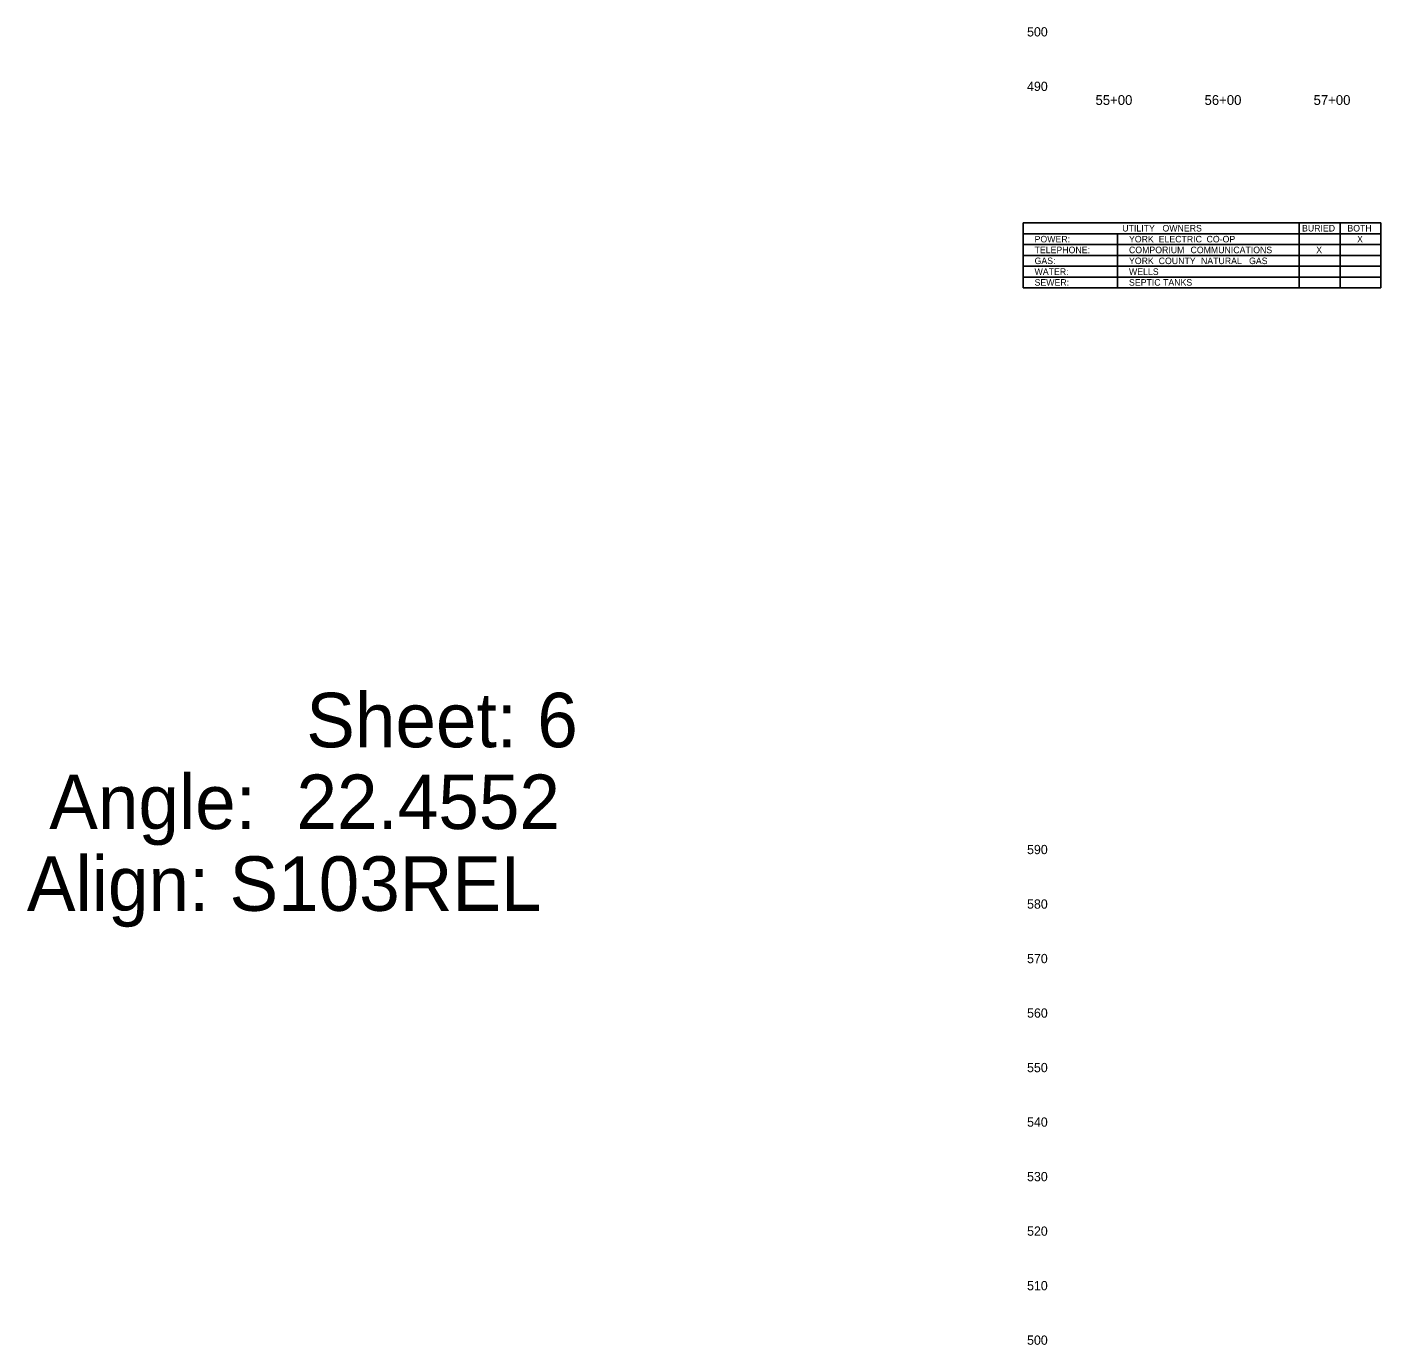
# Model space of a CAD drawing. Extents: x 1964849 to 1967422, y 1116563 to 1122211.
# Drawn here: x 1964849 to 1966090, y 1116575 to 1117784 of the extents above; entities that cross this region are included whole.
import ezdxf

# ---------------------------------------------------------------- set-up
doc = ezdxf.new("R2010")
doc.units = 0
for name, color, linetype in [('RD_DDB_Profile_Elev', 7, 'Continuous'), ('RD_DDB_StaTX', 7, 'Continuous'), ('RD_PD_Final_TX', 7, 'Continuous'), ('RD_TX_Misc1', 7, 'Continuous')]:
    doc.layers.add(name, color=color, linetype=linetype)

msp = doc.modelspace()

# ---------------------------------------------------------------- linework, layer by layer
at = {"layer": 'RD_PD_Final_TX'}
msp.add_line((1965762.3, 1117604.7), (1965762.3, 1117604.7), dxfattribs=at)
at = {"layer": 'RD_TX_Misc1'}
for p, q in [((1965762.3, 1117604.7), (1966090.5, 1117604.7)), ((1965762.3, 1117545), (1965762.3, 1117604.7)), ((1966015.6, 1117545), (1966015.6, 1117604.7)), ((1966053, 1117545), (1966053, 1117604.7)), ((1966090.5, 1117545), (1966090.5, 1117604.7)), ((1965762.3, 1117594.7), (1966090.5, 1117594.7)), ((1965762.3, 1117584.8), (1966090.5, 1117584.8)), ((1965848.9, 1117545), (1965848.9, 1117594.7)), ((1965762.3, 1117574.8), (1966090.5, 1117574.8)), ((1965762.3, 1117564.9), (1966090.5, 1117564.9)), ((1965762.3, 1117554.9), (1966090.5, 1117554.9)), ((1965762.3, 1117545), (1966090.5, 1117545))]:
    msp.add_line(p, q, dxfattribs=at)

# ---------------------------------------------------------------- texts
at = {"layer": 'RD_DDB_Profile_Elev'}
for s, p in [('500', (1965765.9, 1117775.6)), ('490', (1965765.9, 1117725.6)), ('590', (1965765.9, 1117025.6)), ('580', (1965765.9, 1116975.6)), ('570', (1965765.9, 1116925.6)), ('560', (1965765.9, 1116875.6)), ('550', (1965765.9, 1116825.6)), ('540', (1965765.9, 1116775.6)), ('530', (1965765.9, 1116725.6)), ('520', (1965765.9, 1116675.6)), ('510', (1965765.9, 1116625.6)), ('500', (1965765.9, 1116575.6))]:
    msp.add_text(s, height=8.5, dxfattribs=at).set_placement(p)
at = {"layer": 'RD_DDB_StaTX'}
for s, p in [('55+00', (1965828.7, 1117712.8)), ('56+00', (1965928.7, 1117712.8)), ('57+00', (1966028.7, 1117712.8))]:
    msp.add_text(s, height=9, dxfattribs=at).set_placement(p)
at = {"layer": 'RD_TX_Misc1'}
for s, height, p in [(' UTILITY', 6, (1965851, 1117596.7)), (' OWNERS', 6, (1965887.9, 1117596.7)), ('BURIED', 6, (1966018.1, 1117596.7)), ('BOTH', 6, (1966059.7, 1117596.7)), ('POWER:', 6, (1965772.8, 1117586.7)), ('YORK', 6, (1965859.4, 1117586.7)), (' ELECTRIC', 6, (1965884.4, 1117586.7)), (' CO-OP', 6, (1965928.3, 1117586.7)), ('X', 6, (1966068.6, 1117586.7)), ('TELEPHONE:', 6, (1965772.8, 1117576.8)), ('GAS:', 6, (1965772.8, 1117566.8)), ('YORK', 6, (1965859.4, 1117566.8)), ('COMPORIUM', 6, (1965859.4, 1117576.8)), (' COUNTY', 6, (1965884.4, 1117566.8)), (' COMMUNICATIONS', 6, (1965913.6, 1117576.8)), (' NATURAL', 6, (1965923.2, 1117566.8)), (' GAS', 6, (1965967.3, 1117566.8)), ('X', 6, (1966031.1, 1117576.8)), ('WATER:', 6, (1965772.8, 1117556.9)), ('WELLS', 6, (1965859.4, 1117556.9)), ('SEWER:', 6, (1965772.8, 1117547)), ('SEPTIC', 6, (1965859.4, 1117547)), (' TANKS', 6, (1965888.4, 1117547)), ('Sheet: 6', 50, (1965104.8, 1117123.6)), ('Angle:  22.4552', 50, (1964869.1, 1117048.6)), ('Align: S103REL', 50, (1964848.6, 1116973.6))]:
    msp.add_text(s, height=height, dxfattribs=at).set_placement(p)

doc.saveas('drawing.dxf')
